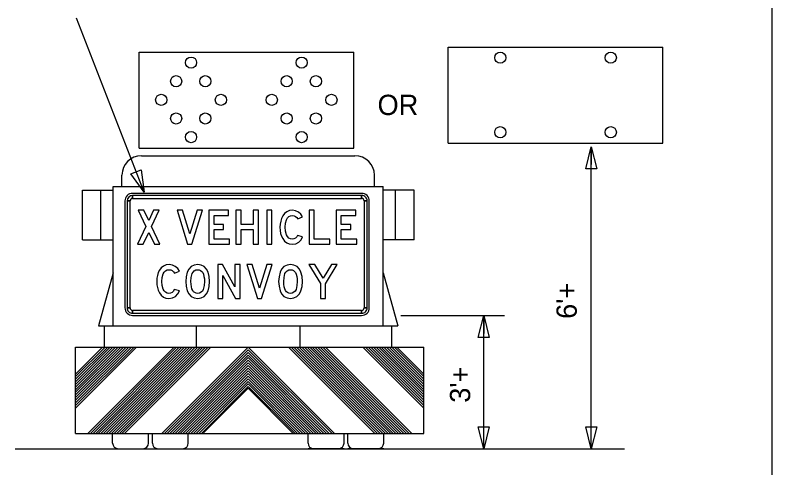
# Model space of a CAD drawing. Extents: x -747 to 834, y -5485 to -3577.
# Drawn here: x 92.9 to 316.6, y -4956.7 to -4822.8 of the extents above; entities that cross this region are included whole.
import ezdxf

# ---------------------------------------------------------------- set-up
doc = ezdxf.new("R2010")
doc.units = 0
doc.layers.add('Working Level 1', color=7, linetype='Continuous')

msp = doc.modelspace()

# ---------------------------------------------------------------- linework, layer by layer
at = {"layer": 'Working Level 1'}
for p, q in [((316.57, -4442.19), (316.57, -5484.51)), ((131, -4875.17), (110.98, -4823.63)), ((129.54, -4833.7), (192.97, -4833.7)), ((129.54, -4862.14), (129.54, -4833.7)), ((192.97, -4862.14), (192.97, -4833.7)), ((220.93, -4860.69), (220.93, -4832.25)), ((220.93, -4832.25), (284.36, -4832.25)), ((284.36, -4860.69), (284.36, -4832.25)), ((129.54, -4862.14), (192.97, -4862.14)), ((220.93, -4860.69), (284.36, -4860.69)), ((263.2, -4951.02), (263.2, -4861.71)), ((263.2, -4861.71), (263.2, -4866.95)), ((130.2, -4864.39), (193.34, -4864.39)), ((124.46, -4873.42), (124.46, -4870.12)), ((199.08, -4873.42), (199.08, -4870.12)), ((121.85, -4914.68), (121.85, -4873.42)), ((121.85, -4873.42), (201.68, -4873.42)), ((201.68, -4914.68), (201.68, -4873.42)), ((112.75, -4889.25), (112.75, -4874.58)), ((112.75, -4874.58), (121.85, -4874.58)), ((118.26, -4889.25), (118.26, -4874.58)), ((195.31, -4875.49), (127.6, -4875.49)), ((127.6, -4876.99), (127.6, -4876.12)), ((195.31, -4876.12), (195.31, -4876.99)), ((210.79, -4874.58), (201.68, -4874.58)), ((205.27, -4889.25), (205.27, -4874.58)), ((210.79, -4889.25), (210.79, -4874.58)), ((125.34, -4877.75), (125.34, -4909.35)), ((125.97, -4877.75), (126.85, -4877.75)), ((196.06, -4877.75), (196.94, -4877.75)), ((197.57, -4909.35), (197.57, -4877.75)), ((112.75, -4889.25), (121.85, -4889.25)), ((210.79, -4889.25), (201.68, -4889.25)), ((121.85, -4898.96), (117.54, -4914.68)), ((201.68, -4898.96), (206, -4914.68)), ((126.85, -4909.35), (125.97, -4909.35)), ((196.94, -4909.35), (196.06, -4909.35)), ((127.6, -4910.98), (127.6, -4910.1)), ((127.6, -4911.6), (195.31, -4911.6)), ((195.31, -4910.1), (195.31, -4910.98)), ((206.94, -4911.6), (237.56, -4911.6)), ((231.39, -4951.02), (231.39, -4911.6)), ((231.39, -4911.6), (231.39, -4916.93)), ((117.54, -4914.68), (206, -4914.68)), ((119.33, -4920.99), (119.33, -4914.68)), ((146.45, -4920.99), (146.45, -4914.8)), ((177.09, -4920.99), (177.09, -4914.8)), ((204.21, -4920.99), (204.21, -4914.68)), ((110.76, -4920.99), (213.71, -4920.99)), ((110.76, -4920.99), (213.71, -4920.99)), ((110.76, -4920.99), (213.71, -4920.99)), ((110.76, -4920.99), (213.71, -4920.99)), ((110.76, -4946.48), (110.76, -4920.99)), ((110.76, -4928.97), (118.74, -4920.99)), ((110.76, -4938.25), (128.02, -4920.99)), ((110.76, -4937.46), (127.24, -4920.99)), ((110.76, -4936.68), (126.46, -4920.99)), ((110.76, -4935.91), (125.69, -4920.99)), ((110.76, -4935.13), (124.91, -4920.99)), ((110.76, -4934.35), (124.13, -4920.99)), ((110.76, -4933.58), (123.36, -4920.99)), ((110.76, -4932.8), (122.58, -4920.99)), ((110.76, -4932.02), (121.79, -4920.99)), ((110.76, -4931.24), (121.01, -4920.99)), ((110.76, -4930.47), (120.24, -4920.99)), ((110.76, -4929.69), (119.46, -4920.99)), ((110.76, -4939.02), (128.77, -4921.01)), ((114.35, -4946.48), (139.85, -4920.99)), ((115.13, -4946.48), (140.63, -4920.99)), ((115.91, -4946.48), (141.41, -4920.99)), ((116.69, -4946.48), (142.19, -4920.99)), ((117.46, -4946.48), (142.96, -4920.99)), ((118.24, -4946.48), (143.74, -4920.99)), ((119.02, -4946.48), (144.52, -4920.99)), ((119.8, -4946.48), (145.3, -4920.99)), ((120.57, -4946.48), (146.07, -4920.99)), ((121.35, -4946.48), (146.85, -4920.99)), ((122.14, -4946.48), (147.63, -4920.99)), ((122.91, -4946.48), (148.4, -4920.99)), ((123.69, -4946.48), (149.18, -4920.99)), ((124.47, -4946.48), (149.95, -4921)), ((125.24, -4946.48), (150.74, -4920.99)), ((136.27, -4946.48), (161.77, -4920.99)), ((187.27, -4946.48), (161.77, -4920.99)), ((199.23, -4946.48), (173.73, -4920.99)), ((200, -4946.48), (174.52, -4921)), ((200.79, -4946.48), (175.29, -4920.99)), ((201.57, -4946.48), (176.07, -4920.99)), ((202.34, -4946.48), (176.84, -4920.99)), ((203.12, -4946.48), (177.62, -4920.99)), ((203.9, -4946.48), (178.4, -4920.99)), ((204.67, -4946.48), (179.17, -4920.99)), ((205.45, -4946.48), (179.95, -4920.99)), ((206.23, -4946.48), (180.73, -4920.99)), ((207.01, -4946.48), (181.51, -4920.99)), ((207.78, -4946.48), (182.28, -4920.99)), ((208.56, -4946.48), (183.06, -4920.99)), ((209.34, -4946.48), (183.85, -4920.99)), ((210.12, -4946.48), (184.62, -4920.99)), ((213.71, -4939.02), (195.7, -4921.01)), ((213.71, -4938.25), (196.45, -4920.99)), ((213.71, -4937.46), (197.23, -4920.99)), ((213.71, -4936.68), (198.01, -4920.99)), ((213.71, -4935.91), (198.78, -4920.99)), ((213.71, -4935.13), (199.56, -4920.99)), ((213.71, -4934.35), (200.35, -4920.99)), ((213.71, -4933.58), (201.12, -4920.99)), ((213.71, -4932.8), (201.9, -4920.99)), ((213.71, -4932.02), (202.68, -4920.99)), ((213.71, -4931.24), (203.46, -4920.99)), ((213.71, -4930.47), (204.23, -4920.99)), ((213.71, -4929.69), (205.01, -4920.99)), ((213.71, -4928.97), (205.73, -4920.99)), ((213.71, -4946.48), (213.71, -4920.99)), ((137.05, -4946.48), (161.77, -4921.76)), ((137.83, -4946.48), (161.77, -4922.54)), ((186.45, -4946.44), (161.77, -4921.76)), ((185.72, -4946.48), (161.77, -4922.54)), ((138.61, -4946.48), (161.77, -4923.32)), ((139.38, -4946.48), (161.77, -4924.09)), ((140.16, -4946.48), (161.77, -4924.87)), ((184.93, -4946.48), (161.77, -4923.32)), ((184.16, -4946.48), (161.77, -4924.09)), ((183.38, -4946.48), (161.77, -4924.87)), ((140.94, -4946.48), (161.77, -4925.66)), ((141.71, -4946.48), (161.77, -4926.43)), ((142.49, -4946.48), (161.77, -4927.21)), ((182.6, -4946.48), (161.77, -4925.66)), ((181.83, -4946.48), (161.77, -4926.43)), ((181.05, -4946.48), (161.77, -4927.21)), ((143.27, -4946.48), (161.77, -4927.99)), ((144.05, -4946.48), (161.77, -4928.77)), ((144.82, -4946.48), (161.77, -4929.54)), ((180.27, -4946.48), (161.77, -4927.99)), ((179.49, -4946.48), (161.77, -4928.77)), ((178.72, -4946.48), (161.77, -4929.54)), ((145.6, -4946.48), (161.77, -4930.32)), ((146.38, -4946.48), (161.77, -4931.1)), ((147.15, -4946.48), (161.77, -4931.87)), ((177.94, -4946.48), (161.77, -4930.32)), ((177.16, -4946.48), (161.77, -4931.1)), ((176.39, -4946.48), (161.77, -4931.87)), ((147.93, -4946.48), (161.77, -4932.65)), ((148.58, -4946.34), (161.77, -4933.15)), ((175.61, -4946.48), (161.77, -4932.65)), ((175.1, -4946.48), (161.77, -4933.15)), ((110.76, -4946.48), (213.71, -4946.48)), ((110.76, -4946.48), (213.71, -4946.48)), ((110.76, -4946.48), (213.71, -4946.48)), ((110.76, -4946.48), (213.71, -4946.48)), ((121.7, -4949.37), (121.7, -4946.48)), ((132.34, -4949.37), (132.34, -4946.48)), ((133.44, -4949.37), (133.44, -4946.48)), ((144.07, -4949.37), (144.07, -4946.48)), ((179.46, -4949.37), (179.46, -4946.48)), ((190.1, -4949.37), (190.1, -4946.48)), ((191.2, -4949.37), (191.2, -4946.48)), ((201.84, -4949.37), (201.84, -4946.48)), ((92.88, -4951.02), (272.99, -4951.02)), ((121.7, -4951.02), (132.34, -4951.02)), ((121.7, -4951.02), (132.34, -4951.02)), ((121.7, -4951.02), (132.34, -4951.02)), ((121.7, -4951.02), (132.34, -4951.02)), ((133.44, -4951.02), (144.07, -4951.02)), ((133.44, -4951.02), (144.07, -4951.02)), ((133.44, -4951.02), (144.07, -4951.02)), ((133.44, -4951.02), (144.07, -4951.02)), ((190.1, -4951.02), (179.46, -4951.02)), ((190.1, -4951.02), (179.46, -4951.02)), ((190.1, -4951.02), (179.46, -4951.02)), ((190.1, -4951.02), (179.46, -4951.02)), ((201.84, -4951.02), (191.2, -4951.02)), ((201.84, -4951.02), (191.2, -4951.02)), ((201.84, -4951.02), (191.2, -4951.02)), ((201.84, -4951.02), (191.2, -4951.02))]:
    msp.add_line(p, q, dxfattribs=at)
for points in [[(261.57, -4868.21), (263.2, -4861.71), (264.82, -4868.21)], [(130.16, -4868.53), (131, -4875.17), (127.13, -4869.7)], [(195.31, -4876.12), (127.6, -4876.12), (127.6, -4876.99), (195.31, -4876.99), (195.31, -4876.12)], [(125.97, -4877.75), (125.97, -4909.35), (126.85, -4909.35), (126.85, -4877.75), (125.97, -4877.75)], [(196.94, -4909.35), (196.94, -4877.75), (196.06, -4877.75), (196.06, -4909.35), (196.94, -4909.35)], [(135.7, -4890.54), (133.21, -4885.28), (135.5, -4880.51), (133.82, -4880.51), (132.37, -4883.53), (130.92, -4880.51), (129.24, -4880.51), (131.53, -4885.29), (129.01, -4890.54), (130.69, -4890.54), (132.36, -4887.05), (134.03, -4890.54)], [(148.23, -4880.51), (146.65, -4880.51), (144.5, -4887.44), (142.35, -4880.51), (140.76, -4880.51), (143.87, -4890.54), (145.12, -4890.54)], [(156.23, -4889.02), (151.68, -4889.02), (151.68, -4886.18), (154.52, -4886.18), (154.52, -4884.67), (151.68, -4884.67), (151.68, -4882.02), (155.93, -4882.02), (155.93, -4880.51), (150.17, -4880.51), (150.17, -4890.54), (156.23, -4890.54)], [(164.79, -4890.54), (164.79, -4880.51), (163.27, -4880.51), (163.27, -4884.67), (159.68, -4884.67), (159.68, -4880.51), (158.16, -4880.51), (158.16, -4890.54), (159.68, -4890.54), (159.68, -4886.18), (163.27, -4886.18), (163.27, -4890.54)], [(168.77, -4890.54), (168.77, -4880.51), (167.26, -4880.51), (167.26, -4890.54)], [(177.87, -4888.31), (176.35, -4887.93), (176.13, -4888.37), (175.76, -4888.72), (175.29, -4888.95), (174.77, -4889.02), (174.24, -4888.94), (173.79, -4888.7), (173.41, -4888.3), (173.1, -4887.75), (172.79, -4886.72), (172.69, -4885.52), (172.79, -4884.32), (173.11, -4883.29), (173.43, -4882.73), (173.82, -4882.34), (174.28, -4882.1), (174.82, -4882.02), (175.32, -4882.09), (175.78, -4882.3), (176.15, -4882.63), (176.41, -4883.05), (177.87, -4882.47), (177.38, -4881.67), (176.66, -4881.04), (175.79, -4880.64), (174.84, -4880.51), (173.96, -4880.61), (173.19, -4880.92), (172.53, -4881.45), (171.98, -4882.18), (171.63, -4882.9), (171.38, -4883.7), (171.22, -4884.57), (171.17, -4885.52), (171.22, -4886.46), (171.37, -4887.33), (171.62, -4888.12), (171.97, -4888.85), (172.51, -4889.59), (173.16, -4890.11), (173.92, -4890.43), (174.79, -4890.54), (175.81, -4890.38), (176.73, -4889.92), (177.44, -4889.21)], [(185.86, -4890.54), (185.86, -4889.02), (181.31, -4889.02), (181.31, -4880.51), (179.8, -4880.51), (179.8, -4890.54)], [(193.85, -4889.02), (189.3, -4889.02), (189.3, -4886.18), (192.14, -4886.18), (192.14, -4884.67), (189.3, -4884.67), (189.3, -4882.02), (193.55, -4882.02), (193.55, -4880.51), (187.79, -4880.51), (187.79, -4890.54), (193.85, -4890.54)], [(141.42, -4904.36), (139.91, -4903.98), (139.68, -4904.42), (139.32, -4904.77), (138.85, -4905), (138.32, -4905.07), (137.8, -4904.99), (137.34, -4904.75), (136.96, -4904.35), (136.66, -4903.8), (136.34, -4902.77), (136.24, -4901.57), (136.35, -4900.37), (136.67, -4899.34), (136.98, -4898.79), (137.37, -4898.39), (137.83, -4898.15), (138.37, -4898.07), (138.87, -4898.14), (139.33, -4898.35), (139.71, -4898.68), (139.97, -4899.1), (141.42, -4898.53), (140.93, -4897.72), (140.22, -4897.09), (139.35, -4896.69), (138.4, -4896.56), (137.51, -4896.66), (136.74, -4896.98), (136.08, -4897.5), (135.54, -4898.23), (135.18, -4898.95), (134.93, -4899.75), (134.78, -4900.62), (134.73, -4901.57), (134.78, -4902.51), (134.93, -4903.38), (135.18, -4904.17), (135.53, -4904.9), (136.06, -4905.64), (136.71, -4906.16), (137.47, -4906.48), (138.35, -4906.59), (139.37, -4906.43), (140.28, -4905.97), (141, -4905.26)], [(150.35, -4901.57), (150.25, -4900.13), (149.95, -4898.79), (149.49, -4897.89), (148.77, -4897.17), (147.87, -4896.71), (146.85, -4896.56), (145.83, -4896.71), (144.92, -4897.17), (144.21, -4897.89), (143.76, -4898.8), (143.45, -4900.14), (143.35, -4901.57), (143.45, -4902.99), (143.76, -4904.33), (144.21, -4905.24), (144.92, -4905.96), (145.83, -4906.43), (146.85, -4906.59), (147.86, -4906.43), (148.77, -4905.97), (149.48, -4905.26), (149.94, -4904.35), (150.25, -4903)], [(148.84, -4901.57), (148.75, -4902.79), (148.48, -4903.92), (148.24, -4904.4), (147.87, -4904.76), (147.39, -4905), (146.86, -4905.07), (146.39, -4905.02), (145.98, -4904.85), (145.64, -4904.58), (145.36, -4904.2), (145.14, -4903.71), (144.99, -4903.1), (144.89, -4902.39), (144.86, -4901.57), (144.95, -4900.36), (145.22, -4899.23), (145.46, -4898.76), (145.83, -4898.39), (146.31, -4898.15), (146.86, -4898.07), (147.32, -4898.13), (147.72, -4898.29), (148.06, -4898.56), (148.34, -4898.95), (148.56, -4899.44), (148.71, -4900.04), (148.81, -4900.75)], [(159.38, -4906.59), (159.38, -4896.56), (157.87, -4896.56), (157.87, -4903.15), (154.21, -4896.56), (152.76, -4896.56), (152.76, -4906.59), (154.27, -4906.59), (154.27, -4899.78), (158.04, -4906.59)], [(168.85, -4896.56), (167.26, -4896.56), (165.11, -4903.49), (162.96, -4896.56), (161.38, -4896.56), (164.49, -4906.59), (165.73, -4906.59)], [(177.78, -4901.57), (177.68, -4900.13), (177.38, -4898.79), (176.92, -4897.89), (176.21, -4897.17), (175.3, -4896.71), (174.28, -4896.56), (173.26, -4896.71), (172.35, -4897.17), (171.64, -4897.89), (171.19, -4898.8), (170.88, -4900.14), (170.78, -4901.57), (170.88, -4902.99), (171.19, -4904.33), (171.64, -4905.24), (172.35, -4905.96), (173.26, -4906.43), (174.28, -4906.59), (175.29, -4906.43), (176.2, -4905.97), (176.91, -4905.26), (177.37, -4904.35), (177.68, -4903)], [(176.27, -4901.57), (176.18, -4902.79), (175.92, -4903.92), (175.67, -4904.4), (175.3, -4904.76), (174.82, -4905), (174.29, -4905.07), (173.82, -4905.02), (173.41, -4904.85), (173.07, -4904.58), (172.79, -4904.2), (172.57, -4903.71), (172.42, -4903.1), (172.33, -4902.39), (172.3, -4901.57), (172.38, -4900.36), (172.65, -4899.23), (172.89, -4898.76), (173.27, -4898.39), (173.74, -4898.15), (174.29, -4898.07), (174.75, -4898.13), (175.15, -4898.29), (175.49, -4898.56), (175.77, -4898.95), (175.99, -4899.44), (176.15, -4900.04), (176.24, -4900.75)], [(188.12, -4896.56), (186.35, -4896.56), (183.89, -4900.56), (181.48, -4896.56), (179.72, -4896.56), (183.12, -4902.19), (183.12, -4906.59), (184.64, -4906.59), (184.64, -4902.23)], [(127.6, -4910.98), (195.31, -4910.98), (195.31, -4910.1), (127.6, -4910.1), (127.6, -4910.98)], [(229.76, -4918.1), (231.39, -4911.6), (233.01, -4918.1)], [(233.01, -4944.52), (231.39, -4951.02), (229.76, -4944.52)], [(264.82, -4944.52), (263.2, -4951.02), (261.57, -4944.52)]]:
    msp.add_lwpolyline(points, close=True, dxfattribs=at)
for centre in [(236.28, -4835.36), (268.95, -4835.36), (144.89, -4836.81), (177.57, -4836.81), (140.48, -4842.32), (149.1, -4842.32), (173.16, -4842.32), (181.78, -4842.32), (136.07, -4847.83), (153.71, -4847.83), (168.75, -4847.83), (186.39, -4847.83), (140.48, -4853.34), (149.1, -4853.34), (173.16, -4853.34), (181.78, -4853.34), (236.28, -4857.4), (268.95, -4857.4), (144.89, -4858.86), (177.57, -4858.86)]:
    msp.add_circle(centre, 1.65, dxfattribs=at)
for centre, radius, start, end in [((130.2, -4870.12), 5.74, 90, 180), ((193.34, -4870.12), 5.74, 0, 90), ((127.6, -4877.75), 2.26, 90.0002, 179.9998), ((127.6, -4877.75), 1.63, 90.0002, 179.9998), ((195.31, -4877.75), 2.26, 0, 90.0002), ((195.31, -4877.75), 1.63, 0, 90.0002), ((127.6, -4877.75), 0.752, 90.0002, 179.9998), ((195.31, -4877.75), 0.752, 0, 90.0002), ((127.6, -4909.35), 2.26, 179.9998, 270.0001), ((127.6, -4909.35), 1.63, 179.9998, 270.0001), ((127.6, -4909.35), 0.752, 179.9998, 270.0001), ((195.31, -4909.35), 2.26, 270.0001, 0.0003), ((195.31, -4909.35), 1.63, 270.0001, 0.0003), ((195.31, -4909.35), 0.752, 270.0001, 0.0003), ((123.35, -4949.37), 1.65, 180, 270), ((130.69, -4949.37), 1.65, 270, 0), ((135.09, -4949.37), 1.65, 180, 270), ((142.42, -4949.37), 1.65, 270, 0), ((181.11, -4949.37), 1.65, 180, 270), ((188.45, -4949.37), 1.65, 270, 0), ((192.85, -4949.37), 1.65, 180, 270), ((200.19, -4949.37), 1.65, 270, 0)]:
    msp.add_arc(centre, radius, start, end, dxfattribs=at)

# ---------------------------------------------------------------- texts
msp.add_text('OR', height=6, dxfattribs=at).set_placement((200.01, -4852.32))
for s, p in [("6'+", (258.9, -4912.62)), ("3'+", (227.4, -4937.43))]:
    msp.add_text(s, height=6, rotation=90, dxfattribs=at).set_placement(p)

doc.saveas('drawing.dxf')
